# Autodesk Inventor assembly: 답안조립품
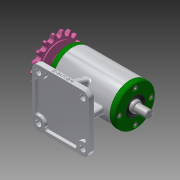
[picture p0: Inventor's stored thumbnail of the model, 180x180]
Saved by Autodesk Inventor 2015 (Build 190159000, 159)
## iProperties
Created: 2019-06
Part Number: 답안조립품
Document SubType Name: Assembly
Designer: a3
Author: a3
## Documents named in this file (11)
- C:\Users\a3\Desktop\490604V1015\답안조립품.iam
- C:\Users\a3\Desktop\490604V1015\본체.ipt
- C:\Users\a3\Desktop\490604V1015\베어링 6203.ipt
- C:\Users\a3\Desktop\490604V1015\축.ipt
- C:\Users\a3\Desktop\490604V1015\커버.ipt
- C:\Users\a3\Desktop\490604V1015\볼트 M4.ipt
- C:\Users\a3\Desktop\490604V1015\키 4x4x12.ipt
- C:\Users\a3\Desktop\490604V1015\스프로킷.ipt
- C:\Users\a3\Desktop\490604V1015\평와셔.ipt
- C:\Users\a3\Desktop\490604V1015\스프링와셔.ipt
- C:\Users\a3\Desktop\490604V1015\오일 실 17 30 5.ipt
